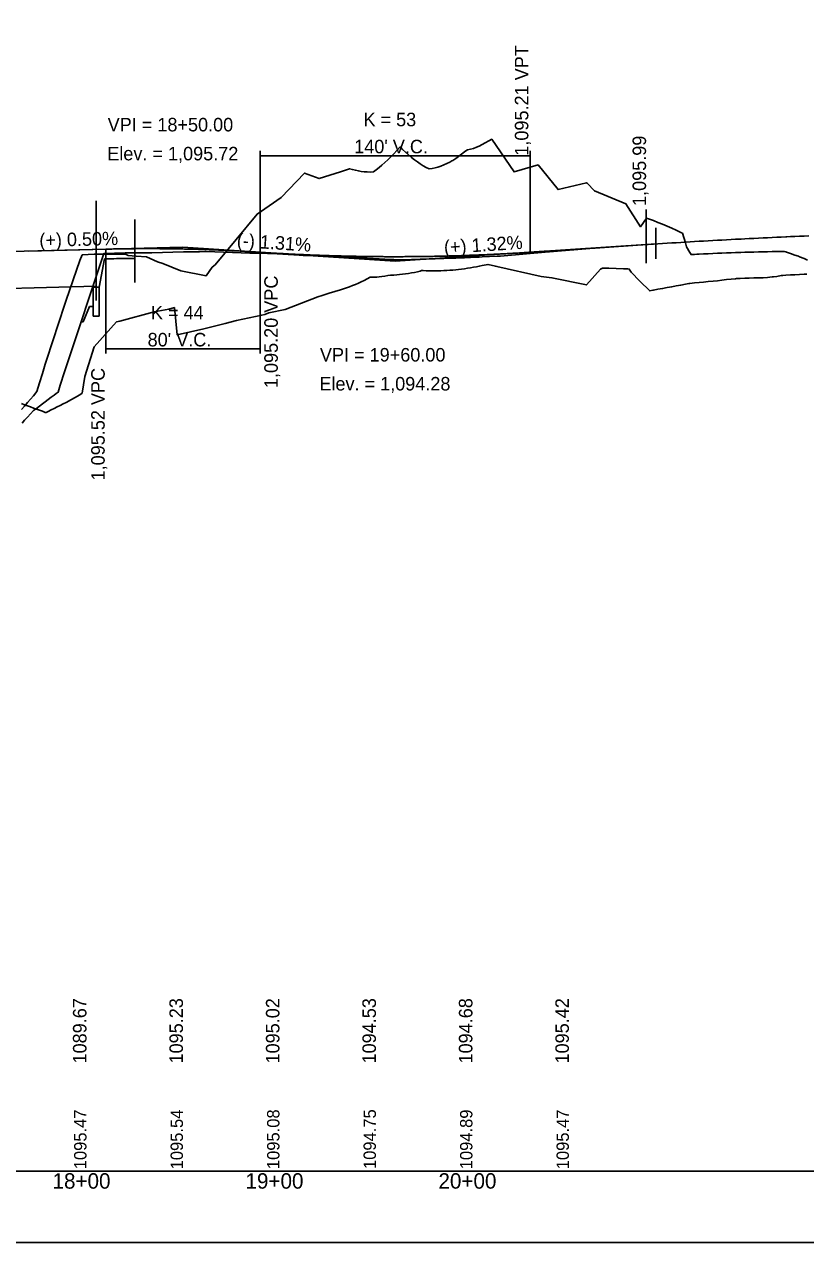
# Model space of a CAD drawing. Extents: x 1545155 to 1547500, y 1196198 to 1197298.
# Drawn here: x 1545923 to 1546328, y 1196198 to 1196829 of the extents above; entities that cross this region are included whole.
import ezdxf

# ---------------------------------------------------------------- set-up
doc = ezdxf.new("R2010")
doc.units = 0
for name, color, linetype in [('BR_CONCRETE', 7, 'Continuous'), ('BR_PROPOSED_TRAVELWAY', 7, 'Continuous'), ('RD_PD_ALT1_TX', 7, 'Continuous'), ('RD_PD_BOC', 7, 'Continuous'), ('RD_PD_CstnLmt', 7, 'Continuous'), ('RD_PD_DR_ErosCtrl', 7, 'Continuous'), ('RD_PD_Final_TrvlWay', 7, 'Continuous'), ('RD_PD_PaveShd', 7, 'Continuous'), ('RD_PD_RW_TX', 7, 'Continuous'), ('RD_SHT_IplotShp', 7, 'Continuous'), ('RD_SHT_ShtClip', 7, 'Continuous'), ('RD_Sketch2', 7, 'Continuous'), ('RD_Sketch8', 7, 'Continuous')]:
    doc.layers.add(name, color=color, linetype=linetype)

msp = doc.modelspace()

# ---------------------------------------------------------------- linework, layer by layer
at = {"layer": 'BR_CONCRETE'}
msp.add_lwpolyline([(1545921.6, 1196622.76), (1545922.89, 1196624.18), (1545924.43, 1196625.86), (1545925.97, 1196627.55), (1545927.51, 1196629.19), (1545929.05, 1196630.35), (1545930.59, 1196631.51), (1545932.13, 1196632.66), (1545933.67, 1196633.81), (1545935.21, 1196634.95), (1545936.75, 1196636.09), (1545938.29, 1196637.23), (1545939.3, 1196637.97), (1545939.83, 1196638.36), (1545940.3, 1196638.71), (1545941.37, 1196642.29), (1545942.07, 1196644.43), (1545942.91, 1196647.27), (1545944.45, 1196651.89), (1545964.02, 1196710.63), (1545975.03, 1196710.87), (1545988.83, 1196710.93), (1546005.27, 1196711.36), (1546013.65, 1196711.42), (1546016.42, 1196711.51), (1546017.09, 1196711.51), (1546039.69, 1196710.81), (1546042.1, 1196710.78), (1546043.77, 1196710.77), (1546053.81, 1196710.36), (1546065.29, 1196709.72), (1546067.31, 1196709.58), (1546083.66, 1196708.93), (1546086.73, 1196708.76), (1546088.26, 1196708.68), (1546089.79, 1196708.6), (1546091.32, 1196708.52), (1546092.15, 1196708.48), (1546092.84, 1196708.46), (1546093.33, 1196708.44), (1546094.37, 1196708.39), (1546095.9, 1196708.31), (1546097.43, 1196708.23), (1546098.96, 1196708.15), (1546100.49, 1196708.07), (1546102.02, 1196708), (1546103.54, 1196707.92), (1546105.07, 1196707.84), (1546106.6, 1196707.76), (1546108.13, 1196707.68), (1546109.66, 1196707.61), (1546111.19, 1196707.53), (1546112.72, 1196707.45), (1546114.24, 1196707.37), (1546115.77, 1196707.29), (1546117.3, 1196707.21), (1546117.73, 1196707.19), (1546118.25, 1196707.2), (1546118.83, 1196707.22), (1546120.36, 1196707.27), (1546121.89, 1196707.33), (1546123.42, 1196707.38), (1546124.94, 1196707.43), (1546126.47, 1196707.49), (1546128, 1196707.55), (1546129.53, 1196707.6), (1546131.06, 1196707.66), (1546132.59, 1196707.72), (1546134.11, 1196707.77), (1546135.64, 1196707.83), (1546137.17, 1196707.89), (1546138.7, 1196707.95), (1546140.23, 1196708.01), (1546141.76, 1196708.07), (1546142.74, 1196708.11), (1546143.29, 1196708.12), (1546144.81, 1196708.14), (1546145.37, 1196708.15), (1546146.34, 1196708.19), (1546147.87, 1196708.25), (1546149.4, 1196708.31), (1546150.93, 1196708.38), (1546152.46, 1196708.45), (1546153.99, 1196708.51), (1546155.51, 1196708.58), (1546157.04, 1196708.65), (1546158.57, 1196708.72), (1546160.1, 1196708.79), (1546167.79, 1196709.15), (1546169.6, 1196709.24), (1546169.6, 1196709.24), (1546194.56, 1196711.39), (1546194.96, 1196711.41), (1546217.86, 1196713.38), (1546218.69, 1196713.4), (1546242.97, 1196715.01), (1546243.38, 1196715.05), (1546248.81, 1196715.41), (1546251.18, 1196715.56), (1546253.54, 1196715.71), (1546255.91, 1196715.86), (1546258.27, 1196716.01), (1546260.64, 1196716.16), (1546263.01, 1196716.3), (1546265.37, 1196716.44), (1546267.87, 1196716.58), (1546270.11, 1196716.73), (1546272.47, 1196716.88), (1546273.67, 1196716.96), (1546274.84, 1196717.02), (1546277.21, 1196717.15), (1546279.57, 1196717.28), (1546281.94, 1196717.4), (1546284.3, 1196717.53), (1546286.67, 1196717.66), (1546289.04, 1196717.78), (1546291.4, 1196717.9), (1546292.83, 1196717.98), (1546293.77, 1196718.02), (1546294.29, 1196718.05), (1546296.14, 1196718.14), (1546298.5, 1196718.26), (1546300.87, 1196718.38), (1546303.24, 1196718.5), (1546305.6, 1196718.62), (1546307.97, 1196718.74), (1546310.33, 1196718.86), (1546312.7, 1196718.98), (1546315.07, 1196719.09), (1546317.43, 1196719.21), (1546317.98, 1196719.24), (1546319.8, 1196719.3), (1546322.17, 1196719.38), (1546324.53, 1196719.46), (1546326.9, 1196719.54), (1546329.27, 1196719.62)], dxfattribs=at)
at = {"layer": 'BR_PROPOSED_TRAVELWAY'}
msp.add_lwpolyline([(1545155, 1197298.22), (1546955, 1197298.22), (1546955, 1196198.22), (1545155, 1196198.22)], close=True, dxfattribs=at)
at = {"layer": 'RD_PD_ALT1_TX'}
msp.add_lwpolyline([(1545921.35, 1196629.69), (1545922.89, 1196631.5), (1545924.43, 1196633.3), (1545925.97, 1196635.1), (1545927.51, 1196636.9), (1545929.31, 1196638.99), (1545930.59, 1196643.54), (1545932.13, 1196648.35), (1545933.67, 1196653.15), (1545935.21, 1196657.93), (1545936.75, 1196662.7), (1545938.29, 1196667.46), (1545939.83, 1196672.21), (1545941.37, 1196676.94), (1545942.91, 1196681.66), (1545944.45, 1196686.37), (1545951.61, 1196706.86), (1545952.78, 1196709.82), (1545959.07, 1196710.25), (1545962.64, 1196710.17), (1545967.84, 1196710.14), (1545975.61, 1196709.99), (1545976.59, 1196709.6), (1545980.7, 1196709.1), (1545986.19, 1196708.9), (1545991.74, 1196706.21), (1545994.51, 1196705.42), (1546003.87, 1196701.49), (1546017.01, 1196698.93), (1546020.08, 1196703.42), (1546021.64, 1196704.73), (1546043.41, 1196730.99), (1546055.83, 1196739.57), (1546067.99, 1196752.24), (1546075.64, 1196749.37), (1546086.73, 1196752.91), (1546088.26, 1196753.4), (1546089.79, 1196753.95), (1546091.32, 1196754.44), (1546092.84, 1196754.01), (1546094.37, 1196753.64), (1546095.9, 1196753.34), (1546097.43, 1196753.1), (1546098.96, 1196752.92), (1546100.49, 1196752.81), (1546102.02, 1196752.76), (1546103.69, 1196752.79), (1546105.07, 1196753.82), (1546106.6, 1196755.03), (1546108.13, 1196756.31), (1546109.66, 1196757.67), (1546111.19, 1196759.1), (1546112.72, 1196760.61), (1546114.24, 1196762.18), (1546115.77, 1196763.84), (1546117.48, 1196765.77), (1546117.84, 1196765.41), (1546118.83, 1196764.42), (1546120.36, 1196762.97), (1546121.89, 1196761.61), (1546123.42, 1196760.32), (1546124.94, 1196759.11), (1546126.47, 1196757.98), (1546128, 1196756.93), (1546129.53, 1196755.96), (1546131.06, 1196755.07), (1546132.59, 1196754.33), (1546134.11, 1196754.58), (1546135.64, 1196754.91), (1546137.17, 1196755.33), (1546138.7, 1196755.85), (1546140.23, 1196756.45), (1546141.76, 1196757.14), (1546143.29, 1196757.93), (1546144.26, 1196758.48), (1546144.81, 1196758.8), (1546146.34, 1196759.76), (1546147.87, 1196760.81), (1546149.4, 1196761.95), (1546150.93, 1196763.18), (1546152.03, 1196764.13), (1546152.46, 1196764.2), (1546153.99, 1196764.55), (1546155.51, 1196765), (1546157.04, 1196765.55), (1546158.57, 1196766.2), (1546160.1, 1196766.96), (1546165.06, 1196769.75), (1546176.64, 1196752.79), (1546189.03, 1196756.4), (1546199.41, 1196743.63), (1546214.06, 1196747.15), (1546214.4, 1196747), (1546218.19, 1196743.03), (1546234.52, 1196736.25), (1546242.09, 1196724.37), (1546245.25, 1196728.88), (1546248.81, 1196727.58), (1546251.18, 1196726.67), (1546253.54, 1196725.72), (1546255.91, 1196724.73), (1546258.27, 1196723.69), (1546260.64, 1196722.61), (1546263.01, 1196721.48), (1546263.87, 1196721.05), (1546265.37, 1196716.15), (1546266.01, 1196714.09), (1546267.74, 1196711), (1546268.31, 1196709.98), (1546270.11, 1196710.08), (1546271.3, 1196710.14), (1546272.47, 1196710.2), (1546274.84, 1196710.32), (1546277.21, 1196710.43), (1546279.57, 1196710.54), (1546281.94, 1196710.65), (1546284.3, 1196710.75), (1546286.67, 1196710.84), (1546289.04, 1196710.93), (1546291.4, 1196711.02), (1546293.77, 1196711.1), (1546294.11, 1196711.11), (1546296.14, 1196711.18), (1546298.5, 1196711.25), (1546300.87, 1196711.32), (1546303.24, 1196711.39), (1546305.6, 1196711.44), (1546307.97, 1196711.5), (1546310.33, 1196711.55), (1546312.7, 1196711.6), (1546315.07, 1196711.64), (1546316.7, 1196711.66), (1546317.43, 1196711.42), (1546317.86, 1196711.28), (1546319.8, 1196710.6), (1546322.17, 1196709.76), (1546323.95, 1196709.13), (1546324.53, 1196708.89), (1546326.9, 1196707.92), (1546328.69, 1196707.18)], dxfattribs=at)
at = {"layer": 'RD_PD_BOC'}
for p, q in [((1545960, 1196693.57), (1545960, 1196712.68)), ((1545961.5, 1196693.16), (1545964.43, 1196707.78)), ((1545980, 1196707.95), (1545980, 1196713.05)), ((1545860, 1196691.07), (1545960, 1196693.57)), ((1545960, 1196693.57), (1545960, 1196693.16)), ((1545956.5, 1196683.16), (1545953.31, 1196675.18)), ((1545958.5, 1196683.16), (1545956.5, 1196683.16)), ((1545952.21, 1196675.18), (1545953.31, 1196675.18))]:
    msp.add_line(p, q, dxfattribs=at)
msp.add_lwpolyline([(1545961.5, 1196693.16), (1545958.5, 1196693.16), (1545958.5, 1196678.16), (1545961.5, 1196678.16)], close=True, dxfattribs=at)
msp.add_open_spline([(1545964.43, 1196707.78), (1545964.65, 1196707.78), (1545966.53, 1196707.82), (1545971.73, 1196707.9), (1545976.69, 1196707.94), (1545980, 1196707.95)], degree=3, dxfattribs=at)
at = {"layer": 'RD_PD_DR_ErosCtrl'}
for p, q in [((1546185, 1196711.21), (1546245, 1196715.16)), ((1545870, 1196710.43), (1545965, 1196712.8))]:
    msp.add_line(p, q, dxfattribs=at)
for points in [[(1545965, 1196712.8), (1545966.6, 1196712.84), (1545968.2, 1196712.88), (1545969.8, 1196712.91), (1545971.4, 1196712.94), (1545973, 1196712.97), (1545974.6, 1196712.99), (1545976.2, 1196713.01), (1545977.8, 1196713.03), (1545979.4, 1196713.05), (1545981, 1196713.06), (1545982.6, 1196713.07), (1545984.2, 1196713.07), (1545985.8, 1196713.08), (1545987.4, 1196713.08), (1545989, 1196713.08), (1545990.6, 1196713.07), (1545992.2, 1196713.06), (1545993.8, 1196713.05), (1545995.4, 1196713.04), (1545997, 1196713.02), (1545998.6, 1196713), (1546000.2, 1196712.98), (1546001.8, 1196712.96), (1546003.4, 1196712.93), (1546005, 1196712.9), (1546006.6, 1196712.86), (1546008.2, 1196712.83), (1546009.8, 1196712.79), (1546011.4, 1196712.75), (1546013, 1196712.7), (1546014.6, 1196712.65), (1546016.2, 1196712.6), (1546017.8, 1196712.55), (1546019.4, 1196712.49), (1546021, 1196712.43), (1546022.6, 1196712.37), (1546024.2, 1196712.3), (1546025.8, 1196712.23), (1546027.4, 1196712.16), (1546029, 1196712.09), (1546030.6, 1196712.01), (1546032.2, 1196711.93), (1546033.8, 1196711.85), (1546035.4, 1196711.76), (1546037, 1196711.67), (1546038.6, 1196711.58), (1546040.2, 1196711.49), (1546041.8, 1196711.39), (1546043.4, 1196711.29), (1546045, 1196711.18)], [(1546045, 1196711.18), (1546047.8, 1196711), (1546050.6, 1196710.83), (1546053.4, 1196710.67), (1546056.2, 1196710.51), (1546059, 1196710.36), (1546061.8, 1196710.22), (1546064.6, 1196710.08), (1546067.4, 1196709.95), (1546070.2, 1196709.83), (1546073, 1196709.72), (1546075.8, 1196709.61), (1546078.6, 1196709.51), (1546081.4, 1196709.42), (1546084.2, 1196709.34), (1546087, 1196709.26), (1546089.8, 1196709.19), (1546092.6, 1196709.13), (1546095.4, 1196709.08), (1546098.2, 1196709.03), (1546101, 1196708.99), (1546103.8, 1196708.96), (1546106.6, 1196708.93), (1546109.4, 1196708.91), (1546112.2, 1196708.9), (1546115, 1196708.9), (1546117.8, 1196708.9), (1546120.6, 1196708.92), (1546123.4, 1196708.93), (1546126.2, 1196708.96), (1546129, 1196708.99), (1546131.8, 1196709.03), (1546134.6, 1196709.08), (1546137.4, 1196709.14), (1546140.2, 1196709.2), (1546143, 1196709.27), (1546145.8, 1196709.35), (1546148.6, 1196709.43), (1546151.4, 1196709.53), (1546154.2, 1196709.63), (1546157, 1196709.73), (1546159.8, 1196709.85), (1546162.6, 1196709.97), (1546165.4, 1196710.1), (1546168.2, 1196710.24), (1546171, 1196710.38), (1546173.8, 1196710.53), (1546176.6, 1196710.69), (1546179.4, 1196710.85), (1546182.2, 1196711.03), (1546185, 1196711.21)]]:
    msp.add_spline(points, degree=3, dxfattribs=at)
at = {"layer": 'RD_PD_RW_TX'}
msp.add_lwpolyline([(1545921.35, 1196632.83), (1545922.89, 1196632.24), (1545924.43, 1196631.66), (1545925.97, 1196631.09), (1545927.51, 1196630.52), (1545929.05, 1196629.95), (1545930.59, 1196629.38), (1545932.13, 1196628.82), (1545933.67, 1196628.26), (1545934.06, 1196628.12), (1545935.21, 1196628.71), (1545936.75, 1196629.5), (1545938.29, 1196630.29), (1545939.83, 1196631.09), (1545941.37, 1196631.88), (1545942.91, 1196632.67), (1545944.45, 1196633.46), (1545951.53, 1196637.35), (1545952.73, 1196638.22), (1545954.16, 1196646.85), (1545959.04, 1196662.15), (1545970.58, 1196675.18), (1545972.33, 1196675.51), (1545990.07, 1196680.41), (1545997.65, 1196681.69), (1546000.59, 1196682.51), (1546001.98, 1196668.48), (1546015.74, 1196671.45), (1546026.89, 1196674.38), (1546032.68, 1196675.91), (1546045.84, 1196678.66), (1546047.4, 1196678.98), (1546049.57, 1196679.77), (1546058.04, 1196681.47), (1546074.96, 1196688.12), (1546077.09, 1196688.85), (1546080.79, 1196689.94), (1546086.73, 1196691.7), (1546088.26, 1196692.2), (1546089.79, 1196692.73), (1546091.32, 1196693.3), (1546092.84, 1196693.9), (1546094.37, 1196694.53), (1546095.9, 1196695.2), (1546097.43, 1196695.9), (1546098.96, 1196696.64), (1546100.49, 1196697.4), (1546102.04, 1196698.22), (1546103.54, 1196698.23), (1546103.95, 1196698.23), (1546104.74, 1196698.21), (1546105.07, 1196698.25), (1546105.5, 1196698.29), (1546106.6, 1196698.44), (1546108.13, 1196698.65), (1546109.66, 1196698.86), (1546111.19, 1196699.08), (1546112.51, 1196699.28), (1546114.24, 1196699.36), (1546115.77, 1196699.46), (1546117.3, 1196699.6), (1546118.83, 1196699.77), (1546120.36, 1196699.97), (1546121.89, 1196700.2), (1546123.42, 1196700.46), (1546124.94, 1196700.75), (1546126.47, 1196701.08), (1546128, 1196701.43), (1546128.68, 1196701.72), (1546129.53, 1196701.68), (1546131.06, 1196701.62), (1546132.59, 1196701.58), (1546134.11, 1196701.56), (1546135.64, 1196701.56), (1546135.95, 1196701.57), (1546137.17, 1196701.59), (1546138.7, 1196701.63), (1546140.23, 1196701.69), (1546141.78, 1196701.78), (1546143.29, 1196701.87), (1546144.81, 1196701.99), (1546146.34, 1196702.13), (1546147.87, 1196702.29), (1546149.4, 1196702.47), (1546150.93, 1196702.67), (1546152.46, 1196702.89), (1546153.99, 1196703.13), (1546155.51, 1196703.39), (1546157.04, 1196703.67), (1546158.57, 1196703.97), (1546160.1, 1196704.29), (1546163.11, 1196704.88), (1546166.89, 1196703.96), (1546167.69, 1196703.85), (1546190.64, 1196698.63), (1546196.24, 1196698), (1546214.06, 1196694.29), (1546221.43, 1196702.4), (1546222.49, 1196702.92), (1546225.64, 1196703.03), (1546233.38, 1196702.62), (1546235.47, 1196702.58), (1546236.32, 1196702.48), (1546237.2, 1196700.92), (1546241.72, 1196696.16), (1546246.88, 1196691.16), (1546248.5, 1196691.54), (1546248.81, 1196691.59), (1546251.18, 1196692), (1546253.54, 1196692.39), (1546255.91, 1196692.87), (1546258.27, 1196693.34), (1546260.64, 1196693.79), (1546263.01, 1196694.23), (1546265.37, 1196694.65), (1546267.1, 1196694.94), (1546267.74, 1196695.02), (1546270.11, 1196695.28), (1546272.47, 1196695.53), (1546274.84, 1196695.77), (1546277.21, 1196695.99), (1546279.72, 1196696.2), (1546281.94, 1196696.48), (1546284.3, 1196696.76), (1546286.67, 1196697.03), (1546289.04, 1196697.28), (1546291.4, 1196697.51), (1546291.88, 1196697.55), (1546293.77, 1196697.64), (1546296.14, 1196697.74), (1546298.5, 1196697.82), (1546300.87, 1196697.88), (1546303.24, 1196697.93), (1546305.6, 1196697.97), (1546307.97, 1196698.19), (1546310.33, 1196698.39), (1546311.11, 1196698.45), (1546312.7, 1196698.71), (1546315.07, 1196699.08), (1546315.94, 1196699.21), (1546317.43, 1196699.3), (1546319.8, 1196699.45), (1546322.17, 1196699.57), (1546324.53, 1196699.68), (1546326.9, 1196699.78), (1546328.23, 1196699.82)], dxfattribs=at)
at = {"layer": 'RD_SHT_IplotShp'}
for p, q in [((1545925.03, 1196711.8), (1546005, 1196713.8)), ((1546084.83, 1196708.58), (1546005, 1196713.8)), ((1546035.17, 1196711.83), (1546115, 1196706.6)), ((1546194.83, 1196711.86), (1546115, 1196706.6))]:
    msp.add_line(p, q, dxfattribs=at)
at = {"layer": 'RD_SHT_ShtClip'}
for p, q in [((1545960, 1196737.82), (1545960, 1196686.21)), ((1546245, 1196733.4), (1546245, 1196705.57)), ((1545980, 1196728.14), (1545980, 1196695.51)), ((1546250, 1196723.91), (1546250, 1196707.8)), ((1546245, 1196715.16), (1546250, 1196715.49))]:
    msp.add_line(p, q, dxfattribs=at)
at = {"layer": 'RD_Sketch2'}
msp.add_line((1545155, 1196235.18), (1547500.39, 1196235.18), dxfattribs=at)
at = {"layer": 'RD_Sketch8'}
for p, q in [((1546045, 1196763.71), (1546045, 1196711.18)), ((1546045, 1196761.21), (1546185, 1196761.21)), ((1546185, 1196763.71), (1546185, 1196711.21)), ((1545965, 1196658.68), (1545965, 1196712.8)), ((1546045, 1196658.68), (1546045, 1196711.18)), ((1545965, 1196661.18), (1546045, 1196661.18))]:
    msp.add_line(p, q, dxfattribs=at)

# ---------------------------------------------------------------- texts
at = {"layer": 'RD_PD_CstnLmt'}
for s, p in [('18+00', (1545937.41, 1196226.18)), ('19+00', (1546037.41, 1196226.18)), ('20+00', (1546137.41, 1196226.18))]:
    msp.add_text(s, height=8, dxfattribs=at).set_placement(p)
at = {"layer": 'RD_PD_Final_TrvlWay'}
for s, height, p in [('1,095.21 VPT', 7, (1546184, 1196761.21)), ('1,095.20 VPC', 7, (1546054.15, 1196640.84)), ('1,095.52 VPC', 7, (1545964.45, 1196593.01)), ('1089.67', 7, (1545955, 1196291.02)), ('1095.23', 7, (1546005, 1196291.02)), ('1095.02', 7, (1546055, 1196291.02)), ('1094.53', 7, (1546105, 1196291.02)), ('1094.68', 7, (1546155, 1196291.02)), ('1095.42', 7, (1546205, 1196291.02)), ('1095.47', 6.4, (1545955, 1196236.24)), ('1095.54', 6.4, (1546005, 1196236.18)), ('1095.08', 6.4, (1546055, 1196236.31)), ('1094.75', 6.4, (1546105, 1196236.36)), ('1094.89', 6.4, (1546155, 1196236.23)), ('1095.47', 6.4, (1546205, 1196236.24))]:
    msp.add_text(s, height=height, rotation=90, dxfattribs=at).set_placement(p)
at = {"layer": 'RD_PD_PaveShd'}
for s, p in [('VPI = 18+50.00', (1545965.98, 1196773.8)), ('Elev. = 1,095.72', (1545965.78, 1196758.8)), ('VPI = 19+60.00', (1546075.98, 1196654.6)), ('Elev. = 1,094.28', (1546075.7, 1196639.6))]:
    msp.add_text(s, height=7, dxfattribs=at).set_placement(p)
msp.add_text('1,095.99', height=7, rotation=90, dxfattribs=at).set_placement((1546245, 1196735.16))
at = {"layer": 'RD_SHT_IplotShp'}
for s, rotation, p in [('(+) 0.50%', 1.4321, (1545930.65, 1196713.94)), ('(-) 1.31%', 356.25495, (1546032.76, 1196713.99)), ('(+) 1.32%', 3.76464, (1546140.49, 1196710.28))]:
    msp.add_text(s, height=7, rotation=rotation, dxfattribs=at).set_placement(p)
at = {"layer": 'RD_Sketch8'}
for s, p in [('K = 53', (1546098.55, 1196776.46)), ("140' V.C.", (1546093.75, 1196762.46)), ('K = 44', (1545988.42, 1196676.43)), ("80' V.C.", (1545986.69, 1196662.43))]:
    msp.add_text(s, height=7, dxfattribs=at).set_placement(p)

doc.saveas('drawing.dxf')
